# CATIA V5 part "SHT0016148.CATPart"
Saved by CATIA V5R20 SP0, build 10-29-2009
Part number: SHT0016148
Bounding box of the stored display mesh (mm): x -544.085 to 25.758, y -634 to -591.5, z 0.9 to 104.4
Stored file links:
  E:\宋国明\项目\02-福田A6-张甲\骨架钣金\2D\宽车主驾底支架\SHT0016148-宽车主驾驶左侧钣金\SHT0016148.CATPart
  C:\Users\hp\Desktop\SHT0016014-宽车主驾驶底部支架焊接总成\SHT0016014.CATPart

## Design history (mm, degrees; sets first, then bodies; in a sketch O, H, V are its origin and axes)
Body1 (main body)
Body2 "SHT0016149-宽车主驾驶右侧钣金"
  Solid1: solid without history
